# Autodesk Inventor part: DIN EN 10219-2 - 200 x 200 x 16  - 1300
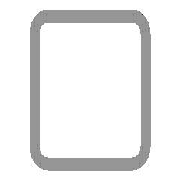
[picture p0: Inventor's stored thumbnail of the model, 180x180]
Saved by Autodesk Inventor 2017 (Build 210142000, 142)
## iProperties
Created: 2016-02
Part Number: DIN EN 10219-2 - 200 x 200 x 16  - 1300
Material: Steel, Mild
Description: Cold formed welded structural hollow sections of non-alloy and fine grain structural steel
Document SubType Name: Modeling
Standard: DIN
Designer: iusti
Standard Revision: 2006-07
Standards Organization: DIN
Language: en-US
Size Designation: 200 x 200 x 16
Categories: <MemberInstance><Categories><Category DisplayName="Structural Shapes" InternalName="089c4875-fa83-4c05-b084-43b9cc11f5ed" Mnemonic="GRDR"><CategoryParameter Dis
Stock Number: 200 x 200 x 16
Mass: 108961 g
Surface Area: 17564.1 cm^2
Volume: 13880.4 cm^3
Density: 7.85 g/cm^3
Appearance: Semi-Polished
_CCFamilyMember: 103
_CCFamilyDisplayName: DIN EN 10219-2 (Square Hollow Section - Cold Formed) - Cold formed welded structural hollow sections of non-alloy and fine grain structural steel
_FrameMemberDoc: Frame Member File
_Version: 15.0.0
_GetPNFromCC: 1
G_W: 200.000 mm
G_H: 200.000 mm
G_L: 1300.000 mm
+452AD748-903E-47FB-AD5B-3293C161C6CB+CUTDETAIL2: Cut
+C5B3B437-76DA-41F1-9D90-B2EA784F79B1+CUTDETAIL3: Cut
IsCustomPart: 1
Author: iusti
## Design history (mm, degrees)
node "Start plane"
node "End plane"
sketch "Sketch"
  geometry: L1 (-100, -52)-(-100, 52); L2 (-52, 100)-(52, 100); L3 (100, 52)-(100, -52); L4 (52, -100)-(-52, -100); L5 (-52, 84)-(52, 84); L6 (84, 52)-(84, -52); L7 (52, -84)-(-52, -84); L8 (-84, -52)-(-84, 52); L9 (0, 153.918)-(0, -153.918) reference; L10 (-153.918, 0)-(153.918, 0) reference; A1 r 48 centre (-52, -52) between (-100, -52) and (-52, -100); A2 r 48 centre (-52, 52) between (-52, 100) and (-100, 52); A3 r 48 centre (52, 52) between (100, 52) and (52, 100); A4 r 48 centre (52, -52) between (52, -100) and (100, -52); A5 r 32 centre (-52, 52) between (-52, 84) and (-84, 52); A6 r 32 centre (52, 52) between (84, 52) and (52, 84); A7 r 32 centre (52, -52) between (52, -84) and (84, -52); A8 r 32 centre (-52, -52) between (-84, -52) and (-52, -84)
  constraints: 16 end point, 16 point on circle, 8 centre point, 8 tangent, 4 parallel, 3 equal radius, 2 perpendicular, 7 other
  dimensions: "d7" = 48 radius of A1 (= G_IR); "d10" = 200 distance between parallel lines of L2 L4 (= G_H); "d11" = 200 distance between parallel lines of L1 L3 (= G_W); "d12" = 16 distance between parallel lines of L3 L6 (= G_T); "d15" = 100 distance between parallel lines of L2 L10 (= 0.5 x d10); "d16" = 100 distance between parallel lines of L9 L3 (= 0.5 x d11)
extrude "Body" new body sketch "Sketch" stored distance "d3" = 1300 (= G_L); taper "d4" = 0 deg
node "Driven Length"
  sketch "Sketch3"
    geometry: L1 (0, 0)-(10, 0) reference
    constraints: 2 end point, 1 horizontal
  workplane "Work Plane3"
  sketch "Sketch4"
    geometry: L1 (-2, 100)-(12, 100) reference; L2 (-2, 1400)-(12, 1400) reference
    dimensions: "d18" = 1300 distance between parallel lines of L1 L2 (derived)
workplane "Work Plane5"
split "Split2"
workplane "Work Plane6"
split "Split3"
body "Solid1"
other parameters: "G_W" = 200 [user parameter; used in 1 equation term], "G_H" = 200 [user parameter; used in 1 equation term], "G_T" = 16 [user parameter; used in 1 equation term], "G_IR" = 48 [user parameter; used in 1 equation term], "G_L" = 1300 (= d18) [user parameter; used in 1 equation term], "d17" = 90 deg
